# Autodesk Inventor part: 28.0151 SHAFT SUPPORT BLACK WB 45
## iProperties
Created: 2007-06
Part Number: 28.0151 SHAFT SUPPORT BLACK WB 45
Material: Aluminum-6061
Document SubType Name: Modeling
Designer: Andy Moles
Density: 2.71 g/cm^3
Author: Andy Moles
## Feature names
1. Extrusion1
2. Extrusion2
